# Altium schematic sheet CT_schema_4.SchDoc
size 556 x 419 mm
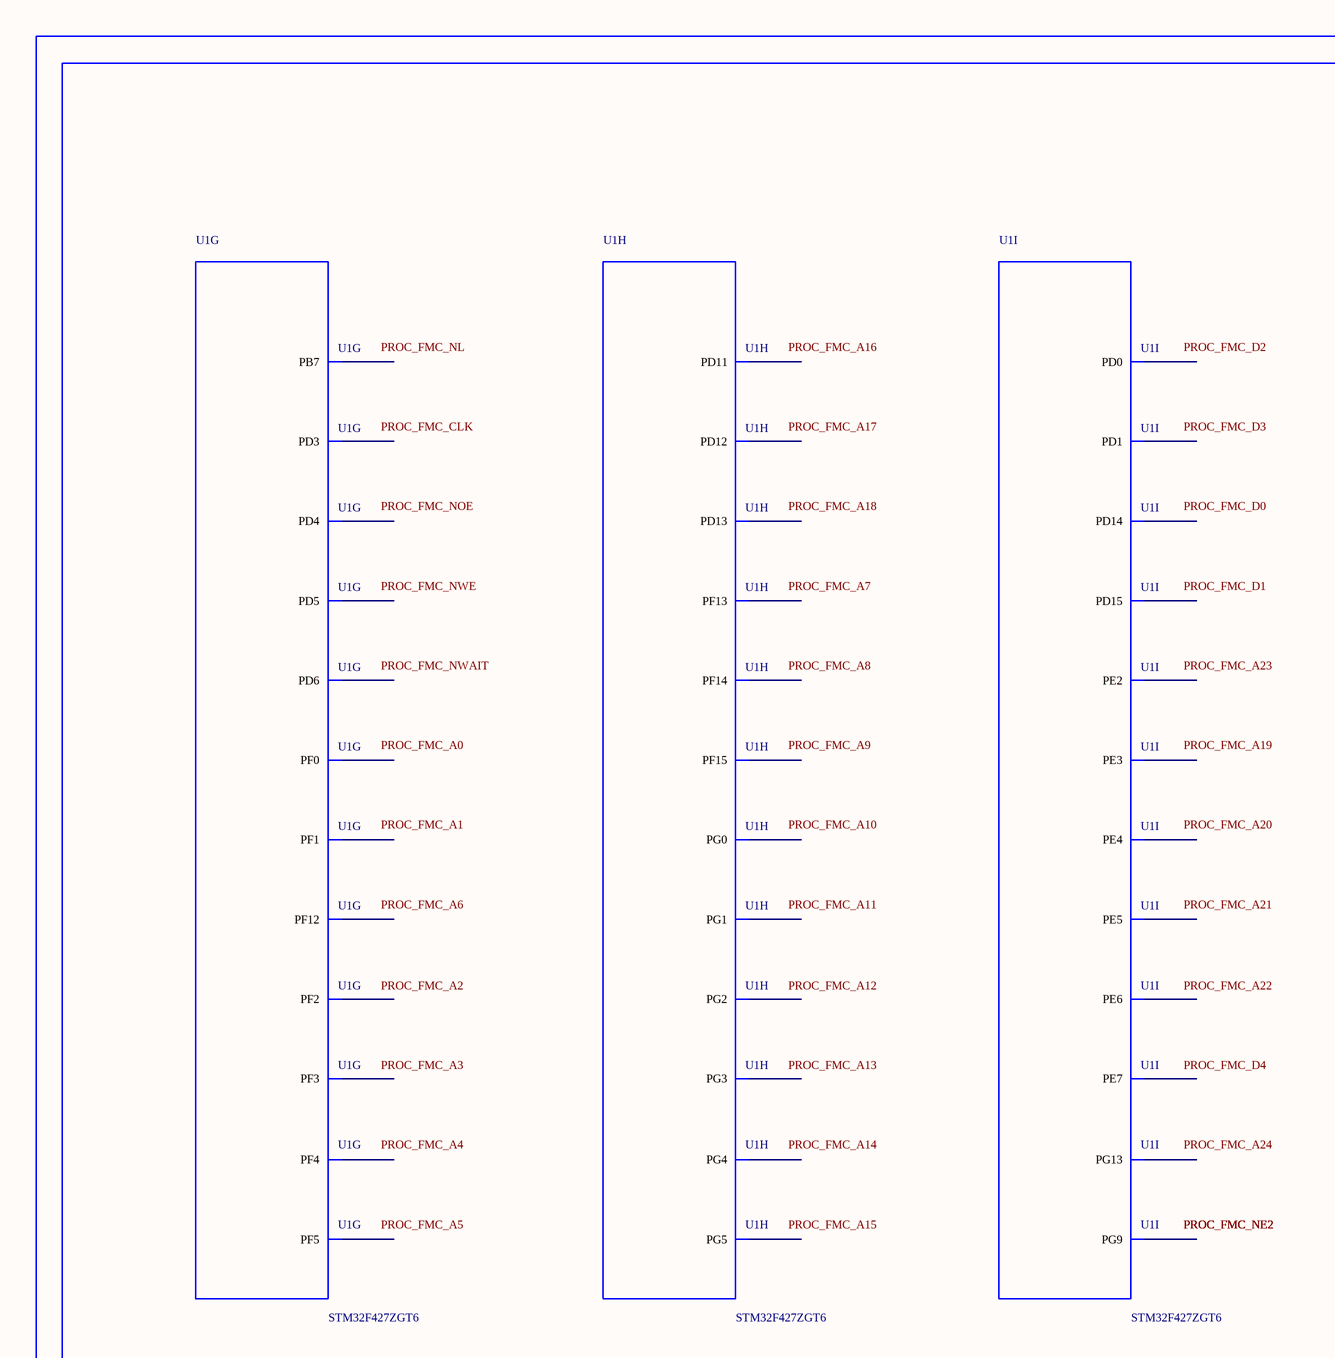
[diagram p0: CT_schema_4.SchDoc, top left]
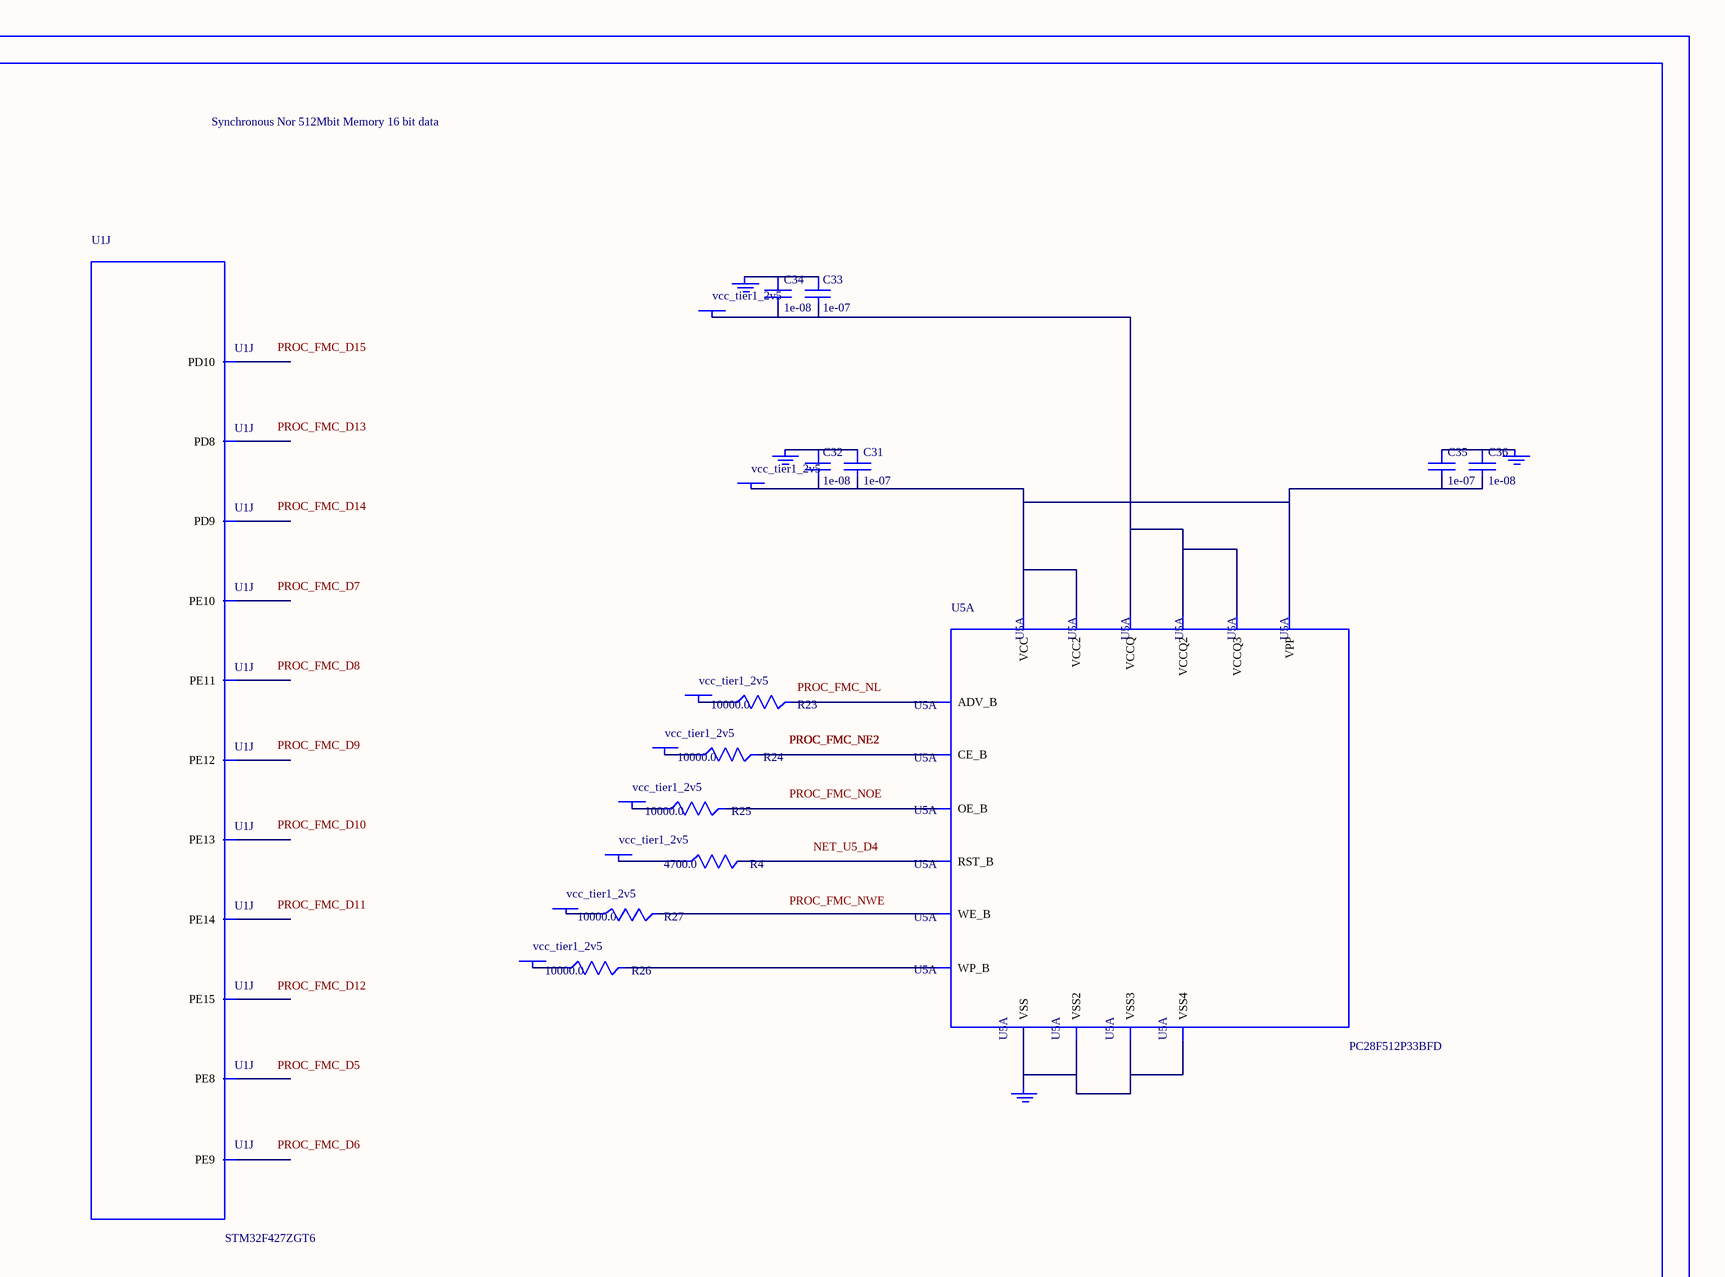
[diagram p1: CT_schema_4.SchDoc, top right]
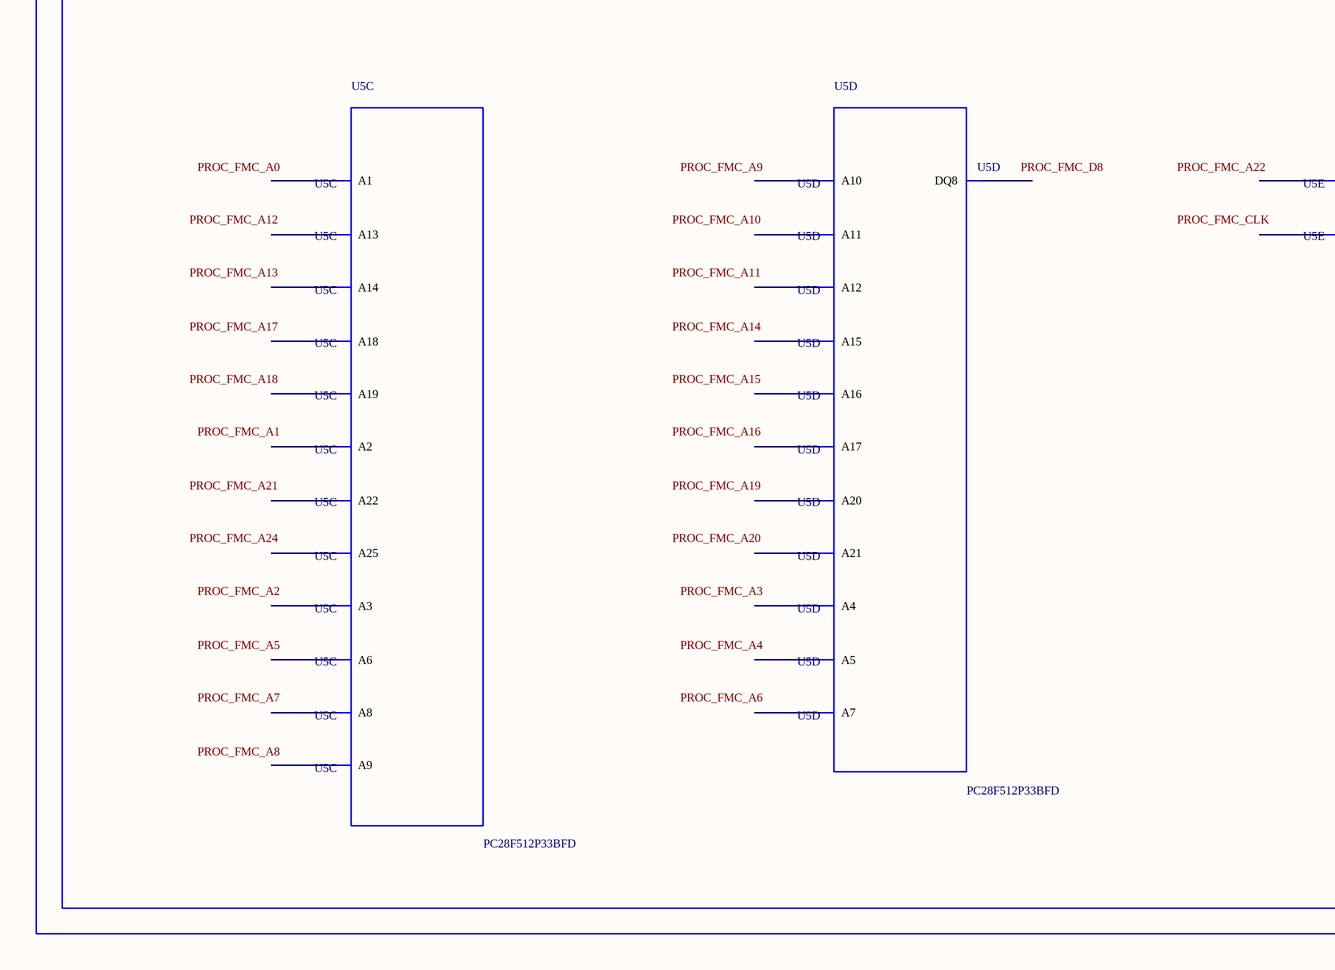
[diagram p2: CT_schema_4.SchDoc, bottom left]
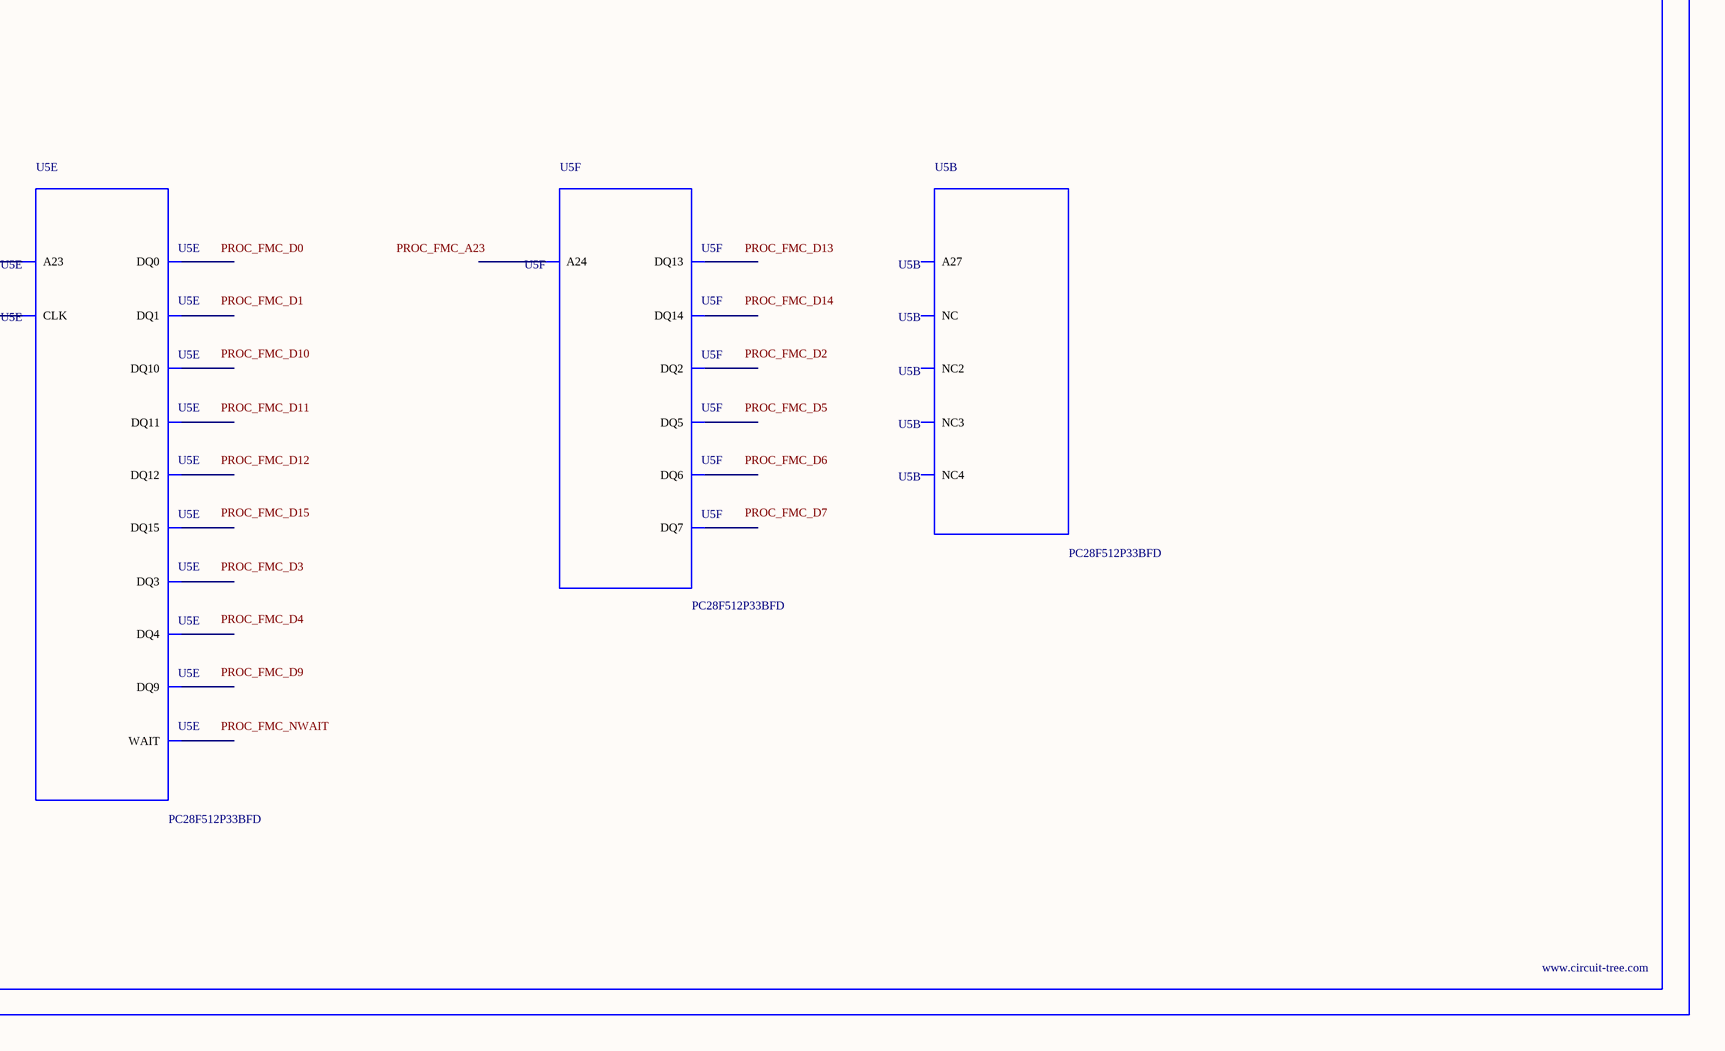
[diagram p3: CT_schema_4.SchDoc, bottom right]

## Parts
BORDER3  (no value)
C31  1e-07  [C0402]
C32  1e-08  [C0402]
C33  1e-07  [C0402]
C34  1e-08  [C0402]
C35  1e-07  [C0402]
C36  1e-08  [C0402]
GND_INSTANCE_3_0  (no value)
GND_INSTANCE_3_1  (no value)
GND_INSTANCE_3_2  (no value)
GND_INSTANCE_3_3  (no value)
POWER_INSTANCE_3_0  vcc_tier1_2v5
POWER_INSTANCE_3_1  vcc_tier1_2v5
POWER_INSTANCE_3_2  vcc_tier1_2v5
POWER_INSTANCE_3_3  vcc_tier1_2v5
POWER_INSTANCE_3_4  vcc_tier1_2v5
POWER_INSTANCE_3_5  vcc_tier1_2v5
POWER_INSTANCE_3_6  vcc_tier1_2v5
POWER_INSTANCE_3_7  vcc_tier1_2v5
R4  4700.0  [R0603]
R23  10000.0  [R0603]
R24  10000.0  [R0603]
R25  10000.0  [R0603]
R26  10000.0  [R0603]
R27  10000.0  [R0603]
U1  STM32F427ZGT6  [LQFP144]  (parts G,H,I,J of 12)
U5  PC28F512P33BFD  [PC28F512P33BFD]  (parts A,B,C,D,E,F of 6)

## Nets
NetC31_1: C31.1 C32.1 GND_INSTANCE_3_0.0(GND)
NetC31_2: C31.2 C32.2 C35.2 C36.2 POWER_INSTANCE_3_0.0(PWR) U5.A4(VPP) U5.A6(VCC) U5.H3(VCC2)
NetC33_1: C33.1 C34.1 GND_INSTANCE_3_1.0(GND)
NetC33_2: C33.2 C34.2 POWER_INSTANCE_3_1.0(PWR) U5.D5(VCCQ) U5.D6(VCCQ2) U5.G4(VCCQ3)
NetC35_1: C35.1 C36.1 GND_INSTANCE_3_2.0(GND)
NetGND_INSTANCE_3_3_0: GND_INSTANCE_3_3.0(GND) U5.B2(VSS) U5.H2(VSS2) U5.H4(VSS3) U5.H6(VSS4)
NetPOWER_INSTANCE_3_2_0: POWER_INSTANCE_3_2.0(PWR) R23.1
NetPOWER_INSTANCE_3_3_0: POWER_INSTANCE_3_3.0(PWR) R24.1
NetPOWER_INSTANCE_3_4_0: POWER_INSTANCE_3_4.0(PWR) R25.1
NetPOWER_INSTANCE_3_5_0: POWER_INSTANCE_3_5.0(PWR) R26.1
NetPOWER_INSTANCE_3_6_0: POWER_INSTANCE_3_6.0(PWR) R27.1
NetPOWER_INSTANCE_3_7_0: POWER_INSTANCE_3_7.0(PWR) R4.1
NetR4_2: R4.2 U5.D4(RST_B)
NetR23_2: R23.2 U5.F6(ADV_B)
NetR24_2: R24.2 U5.B4(CE_B)
NetR25_2: R25.2 U5.F8(OE_B)
NetR26_2: R26.2 U5.C6(WP_B)
NetR27_2: R27.2 U5.G8(WE_B)

Not connected (* = marked no-connect by the designer): U1 1(PE2) 2(PE3) 3(PE4) 4(PE5) 5(PE6) 10(PF0) 11(PF1) 12(PF2) 13(PF3) 14(PF4) 15(PF5) 50(PF12) 53(PF13) 54(PF14) 55(PF15) 56(PG0) 57(PG1) 58(PE7) 59(PE8) 60(PE9) 63(PE10) 64(PE11) 65(PE12) 66(PE13) 67(PE14) 68(PE15) 77(PD8) 78(PD9) 79(PD10) 80(PD11) 81(PD12) 82(PD13) 85(PD14) 86(PD15) 87(PG2) 88(PG3) 89(PG4) 90(PG5) 114(PD0) 115(PD1) 117(PD3) 118(PD4) 119(PD5) 122(PD6) 124(PG9) 128(PG13) 137(PB7); U5 A1 A2(A6) A3(A8) A5(A13) A7(A18) A8(A22) B1(A2) B3(A9) B5(A14) B6(A25) B7(A19) B8(NC) C1(A3) C2(A7) C3(A10) C4(A12) C5(A15) C7(A20) C8(A21) D1(A4) D2(A5) D3(A11) D7(A16) D8(A17) E1(DQ8) E2(DQ1) E3(DQ9) E4(DQ3) E5(DQ4) E6(CLK) E7(DQ15) E8(NC2) F1(NC3) F2(DQ0) F3(DQ10) F4(DQ11) F5(DQ12) F7(WAIT) G1(A23) G2(NC4) G3(DQ2) G5(DQ5) G6(DQ6) G7(DQ14) H1(A27) H5(DQ13) H7(DQ7) H8(A24)

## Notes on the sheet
- Labels drawn without touching a wire or pin: NET_U5_D4, PROC_FMC_A0, PROC_FMC_A1, PROC_FMC_A2, PROC_FMC_A3, PROC_FMC_A4, PROC_FMC_A5, PROC_FMC_A6, PROC_FMC_A7, PROC_FMC_A8, PROC_FMC_A9, PROC_FMC_A10, PROC_FMC_A11, PROC_FMC_A12, PROC_FMC_A13, PROC_FMC_A14, PROC_FMC_A15, PROC_FMC_A16, PROC_FMC_A17, PROC_FMC_A18, PROC_FMC_A19, PROC_FMC_A20, PROC_FMC_A21, PROC_FMC_A22, PROC_FMC_A23, PROC_FMC_A24, PROC_FMC_CLK, PROC_FMC_D0, PROC_FMC_D1, PROC_FMC_D2, PROC_FMC_D3, PROC_FMC_D4, PROC_FMC_D5, PROC_FMC_D6, PROC_FMC_D7, PROC_FMC_D8, PROC_FMC_D9, PROC_FMC_D10, PROC_FMC_D11, PROC_FMC_D12, PROC_FMC_D13, PROC_FMC_D14, PROC_FMC_D15, PROC_FMC_NL, PROC_FMC_NOE, PROC_FMC_NWAIT, PROC_FMC_NWE

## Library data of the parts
BORDER3 = BORDER_PAGE3
C31 C33 C35 = C0402C104K3RACTU
C32 C34 C36 = C0402C103K3RAC
GND_INSTANCE_3_0-GND_INSTANCE_3_3 = GND
POWER_INSTANCE_3_0-POWER_INSTANCE_3_7 = PWR
R4 = RC0603JR-074K7L
R23-R27 = RC0603JR-0710KL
